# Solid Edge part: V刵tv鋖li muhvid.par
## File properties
Author: KULL
Template: Iso Metric Part.par
Last saved by: KULL
Revision: 7
Application: Solid Edge
Accuracy: 0,990
Face Style: Model Default
Fill Style: Normal
Coef. of Thermal Exp: 0.0
Thermal Conductivity: 0.0
Specific Heat: 0.0
Modulus of Elasticity: 0.0
Poisson's Ratio: 0.0
Yield Stress: 0.0
Ultimate Stress: 0.0
Elongation: 0.0
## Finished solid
Body 1: solid body, 6 faces, 6 edges, 0 vertices.
  Faces by surface: cylinder 2, plane 2, torus 2
  Edges by curve: circle 6
Bounding box of the edges (mm; curved faces can reach further): 6.000 x 8.000 x 8.000, from (-12, -4, 34.6638) to (-6, 4, 42.6638).
Cylindrical faces by radius (mm): R2.7 x1, R4 x1
Toroidal faces (ring radius, tube radius in mm): R3.8 r0.2 x2
Planar faces by outward normal: +x 1, -x 1
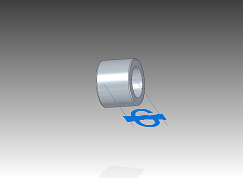
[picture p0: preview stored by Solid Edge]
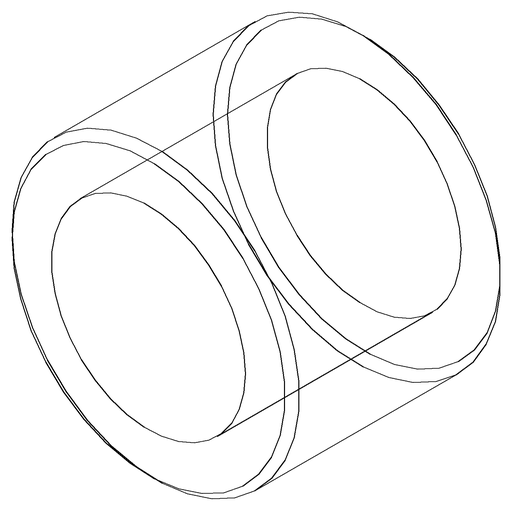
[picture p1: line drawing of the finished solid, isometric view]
